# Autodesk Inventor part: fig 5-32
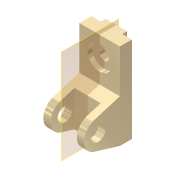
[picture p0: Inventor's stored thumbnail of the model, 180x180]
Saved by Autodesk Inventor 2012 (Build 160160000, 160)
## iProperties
Shininess: 65.0
Angle Display Precision: 2
Document Length Units: 11269
Document Angle Units: 11279
Document Time Units: 11290
Document Mass Units: 11283
Document Length Units Precision: 3
Document Angle Units Precision: 2
Created: 2001-11
Part Number: fig 5-32
Document SubType Name: Modeling
Designer: Renu Muthoo
Density: 1 g/cm^3
Material: Default
Density: 0.0
Volumn: 0.0
Area: 0.0
PropertySet Name: Model Information
Control State: 0
Master: False
Checked Out: False
Author: Renu Muthoo
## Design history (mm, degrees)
node "Sketch1"
sketch "Sketch2"
  geometry: L1 (33.257, 104.664)-(33.257, -75.336); L2 (33.257, -75.336)-(8.257, -75.336); L3 (8.257, -75.336)-(-45.451, -59.045); L4 (-45.451, -1.628)-(8.257, 14.664); L5 (8.257, 14.664)-(8.257, 104.664); L6 (8.257, 104.664)-(33.257, 104.664); C1 r 15 at (-36.743, -30.336); A1 r 30 centre (-36.743, -30.336) between (-45.451, -1.628) and (-45.451, -59.045)
  constraints: 12 end point, 2 centre point, 2 equal length, 2 parallel, 2 point on circle, 2 tangent, 1 coincident, 1 perpendicular, 1 vertical
  dimensions: "d0" = 180 distance of L1.start L1.end; "d1" = 30 radius of A1; "d2" = 25 distance of L5.end L1.start; "d3" = 45 distance from line of L2 A1.centre; "d4" = 70 distance from line of L1 A1.centre; "d5" = 30 diameter of C1
extrude "Extrusion1" new body sketch "Sketch2" distance "d6" = 85; taper "d7" = 0 deg
workplane "Work Plane1"
sketch "Sketch3"
  geometry: L1 (15, 62.364)-(70, 62.364); L2 (70, 62.364)-(70, -52.386); L3 (70, -52.386)-(15, -52.386); L4 (15, -52.386)-(15, 62.364); L5 (0, -45)-(0, -28.708) reference
  constraints: 8 end point, 2 parallel, 1 horizontal, 1 perpendicular
  dimensions: "d8" = 55 distance of L1.start L1.end; "d9" = 15 distance between parallel lines of L5 L4
extrude "Extrusion2" cut sketch "Sketch3" distance "d10" = 50; taper "d11" = 0 deg
sketch "Sketch4"
  geometry: L1 (0, 25)-(85, 25) reference; L2 (0, 0)-(0, 25) reference; L3 (20, 25)-(65, 25); L4 (65, 25)-(65, 35); L5 (65, 35)-(20, 35); L6 (20, 35)-(20, 25)
  constraints: 8 end point, 2 parallel, 1 horizontal, 1 perpendicular, 1 point on line
  dimensions: "d12" = 45 distance of L4.end L5.end; "d13" = 10 distance of L3.end L4.end; "d14" = 20 distance between parallel lines of L2 L6
extrude "Extrusion3" join sketch "Sketch4" stored distance "d15" = 50; taper "d16" = 0 deg
sketch "Sketch5"
  geometry: L1 (85, 0)-(85, 90) reference; L2 (0, 90)-(85, 90) reference; 1 further point
  dimensions: "d17" = 42 distance from line of L2 point (42.5, 48); "d18" = 42.5 distance from line of L1 point (42.5, 48)
hole "Hole1" sketch "Sketch5" at (42.5, 48) diameter "d19" = 20; stored, may be unused: countersink angle "d23" = 82 deg, drill point angle "d25" = 118 deg; dims "d20" = 6, "d21" = 50, "d22" = 10, "d24" = 8
workplane "Work Plane5"
body "Solid1"
